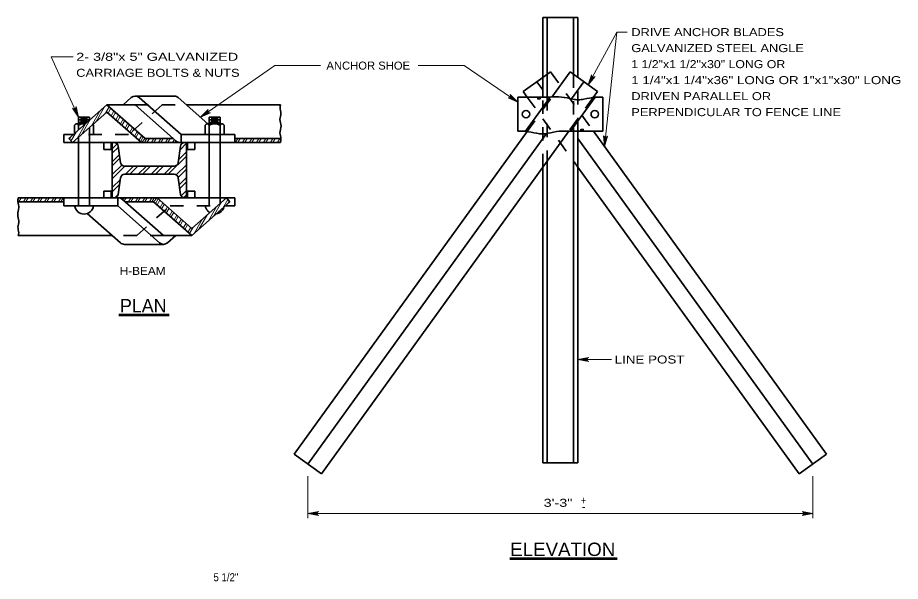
# Model space of a CAD drawing. Extents: x -38.29 to -31.67, y 88.17 to 97.95.
# Drawn here: x -38.29 to -31.67, y 93.73 to 97.95 of the extents above; entities that cross this region are included whole.
import ezdxf
from ezdxf.enums import TextEntityAlignment as Align

# ---------------------------------------------------------------- set-up
doc = ezdxf.new("R2010")
doc.units = 0
doc.header["$LTSCALE"] = 0.024
doc.linetypes.add('SHORT_DASHED', pattern=[2.7, 1.5, -1.2])
for name, color, linetype, lineweight in [('1', 7, 'Continuous', 35), ('10', 7, 'Continuous', 13), ('12', 7, 'Continuous', 53), ('6', 7, 'Continuous', 13)]:
    doc.layers.add(name, color=color, linetype=linetype, lineweight=lineweight)

msp = doc.modelspace()

# ---------------------------------------------------------------- linework, layer by layer
at = {"layer": '1'}
for p, q in [((-34.35494, 97.95427), (-34.09231, 97.95427)), ((-34.35494, 97.95427), (-34.35494, 97.35879)), ((-34.32212, 97.35879), (-34.32212, 97.95427)), ((-34.12515, 97.52935), (-34.12515, 97.95427)), ((-34.09231, 97.95427), (-34.09231, 97.50565)), ((-34.5016, 97.39975), (-34.35494, 97.50565)), ((-34.1504, 97.54758), (-34.28675, 97.35879)), ((-33.94567, 97.39975), (-34.1504, 97.54758)), ((-34.39923, 97.47367), (-34.35494, 97.41233)), ((-34.14069, 97.34537), (-34.04802, 97.47367)), ((-34.50158, 97.39975), (-34.47202, 97.35879)), ((-33.94567, 97.39975), (-33.9771, 97.35621)), ((-37.44183, 97.3544), (-37.50337, 97.3001)), ((-37.41177, 97.36577), (-37.11883, 97.36577)), ((-37.38169, 97.3544), (-37.06833, 97.0779)), ((-37.08877, 97.3544), (-36.86698, 97.15871)), ((-34.542, 97.35879), (-34.542, 97.10225)), ((-34.542, 97.35879), (-34.29921, 97.35879)), ((-34.29921, 97.35879), (-34.48448, 97.10225)), ((-33.96279, 97.35879), (-34.14806, 97.10225)), ((-33.96279, 97.35879), (-33.90527, 97.35879)), ((-33.90527, 97.35879), (-33.90527, 97.10225)), ((-37.62387, 97.3001), (-37.91006, 97.04758)), ((-37.6239, 97.24621), (-37.88333, 97.01729)), ((-37.6239, 97.24621), (-37.36444, 97.01729)), ((-37.62387, 97.3001), (-37.41177, 97.3001)), ((-37.62387, 97.3001), (-37.33771, 97.04758)), ((-37.41177, 97.3001), (-37.10412, 97.02867)), ((-37.02723, 97.3001), (-36.32283, 97.3001)), ((-37.836, 97.20921), (-37.75521, 97.20921)), ((-37.836, 97.20921), (-37.836, 97.15871)), ((-37.836, 97.189), (-37.75521, 97.189)), ((-37.82142, 97.1991), (-37.76979, 97.1991)), ((-37.82142, 97.17892), (-37.76979, 97.17892)), ((-37.75521, 97.20921), (-37.75521, 97.18423)), ((-36.85621, 97.20921), (-36.7754, 97.20921)), ((-36.85621, 97.20921), (-36.85621, 97.15871)), ((-36.85621, 97.189), (-36.7754, 97.189)), ((-36.8416, 97.1991), (-36.79, 97.1991)), ((-36.8416, 97.17892), (-36.79, 97.17892)), ((-36.7754, 97.20921), (-36.7754, 97.15871)), ((-37.86631, 97.14894), (-37.86631, 97.08621)), ((-37.836, 97.16881), (-37.77269, 97.16881)), ((-37.836, 97.14894), (-37.836, 97.11294)), ((-36.88652, 97.14894), (-36.88652, 97.0779)), ((-36.85621, 97.16881), (-36.7754, 97.16881)), ((-36.85621, 97.14894), (-36.85621, 97.0779)), ((-36.7754, 97.14894), (-36.7754, 97.0779)), ((-36.7451, 97.14894), (-36.7451, 97.0779)), ((-37.94712, 97.01729), (-37.94712, 97.0779)), ((-37.94712, 97.0779), (-37.87571, 97.0779)), ((-37.91006, 97.04758), (-37.88333, 97.01729)), ((-37.33771, 97.04758), (-37.36444, 97.01729)), ((-37.33771, 97.04758), (-37.12558, 97.04758)), ((-37.06833, 97.0779), (-37.06833, 97.01729)), ((-37.06833, 97.0779), (-36.66429, 97.0779)), ((-36.66429, 97.0779), (-36.66429, 97.01729)), ((-36.66429, 97.04758), (-36.31919, 97.04758)), ((-34.47346, 97.10027), (-36.22031, 94.68156)), ((-36.11794, 94.60762), (-34.32867, 97.0851)), ((-34.16052, 97.10225), (-36.01558, 94.53371)), ((-34.542, 97.10225), (-34.48448, 97.10225)), ((-34.14806, 97.10225), (-33.90527, 97.10225)), ((-34.12515, 94.6176), (-34.12515, 97.10225)), ((-34.09231, 97.10225), (-34.09231, 94.6176)), ((-34.09231, 97.04871), (-32.32931, 94.60762)), ((-33.97525, 97.10225), (-32.22696, 94.68156)), ((-37.94712, 97.01729), (-36.32283, 97.01729)), ((-37.836, 96.60315), (-37.836, 97.01729)), ((-37.75521, 96.60315), (-37.75521, 97.01729)), ((-37.6466, 96.96679), (-37.6466, 97.01729)), ((-37.59106, 96.96679), (-37.59106, 97.01729)), ((-37.58348, 96.60315), (-37.58348, 97.01729)), ((-37.58348, 97.01729), (-37.56935, 97.01729)), ((-37.53935, 96.99127), (-37.52154, 96.86654)), ((-37.08987, 96.86654), (-37.07204, 96.99127)), ((-37.04204, 97.01729), (-37.02792, 97.01729)), ((-37.02792, 96.60315), (-37.02792, 97.01729)), ((-37.02035, 96.96679), (-37.02035, 97.01729)), ((-36.96479, 96.96679), (-36.96479, 97.01729)), ((-36.85621, 96.60315), (-36.85621, 97.01729)), ((-36.7754, 96.60315), (-36.7754, 97.01729)), ((-37.6466, 96.96679), (-37.59106, 96.96679)), ((-37.02035, 96.96679), (-36.96479, 96.96679)), ((-34.32212, 94.6176), (-34.32212, 96.8785)), ((-37.49154, 96.84052), (-37.11985, 96.84052)), ((-37.49154, 96.77992), (-37.11985, 96.77992)), ((-34.35494, 96.83306), (-34.35494, 94.6176)), ((-34.09231, 96.83306), (-32.43169, 94.53371)), ((-37.52154, 96.7539), (-37.53935, 96.62917)), ((-37.07204, 96.62917), (-37.08987, 96.7539)), ((-37.6466, 96.65365), (-37.59106, 96.65365)), ((-37.6466, 96.60315), (-37.6466, 96.65365)), ((-37.59106, 96.60315), (-37.59106, 96.65365)), ((-37.02035, 96.65365), (-36.96479, 96.65365)), ((-37.02035, 96.60315), (-37.02035, 96.65365)), ((-36.96479, 96.60315), (-36.96479, 96.65365)), ((-36.66429, 96.60315), (-38.28856, 96.60315)), ((-37.94712, 96.54254), (-37.94712, 96.60315)), ((-37.56935, 96.60315), (-37.58348, 96.60315)), ((-37.56935, 96.60315), (-37.58348, 96.60315)), ((-37.54308, 96.54254), (-37.54308, 96.60315)), ((-37.19965, 96.32033), (-37.50727, 96.59177)), ((-37.27371, 96.57285), (-37.24698, 96.60315)), ((-36.98752, 96.37423), (-37.24698, 96.60315)), ((-37.02792, 96.60315), (-37.04204, 96.60315)), ((-37.02792, 96.60315), (-37.04204, 96.60315)), ((-36.98752, 96.37423), (-36.72806, 96.60315)), ((-36.70133, 96.57285), (-36.72806, 96.60315)), ((-36.66429, 96.60315), (-36.66429, 96.54254)), ((-37.94712, 96.57285), (-38.29223, 96.57285)), ((-37.54308, 96.54254), (-37.94712, 96.54254)), ((-37.22971, 96.26604), (-37.54308, 96.54254)), ((-37.27371, 96.57285), (-37.48583, 96.57285)), ((-36.98752, 96.32033), (-37.27371, 96.57285)), ((-36.98752, 96.32033), (-36.70133, 96.57285)), ((-36.66429, 96.54254), (-36.73569, 96.54254)), ((-37.52265, 96.26604), (-37.7719, 96.48598)), ((-37.58417, 96.32033), (-38.28856, 96.32033)), ((-36.98752, 96.32033), (-37.19965, 96.32033)), ((-37.16956, 96.26604), (-37.10804, 96.32033)), ((-37.19965, 96.25469), (-37.49256, 96.25469)), ((-36.01558, 94.53371), (-36.22031, 94.68156)), ((-32.43169, 94.53371), (-32.22696, 94.68156)), ((-34.35494, 94.6176), (-34.09231, 94.6176))]:
    msp.add_line(p, q, dxfattribs=at)
at = {"layer": '1', "linetype": 'SHORT_DASHED'}
for p, q in [((-34.29688, 97.54758), (-34.35494, 97.50565)), ((-34.29688, 97.54758), (-33.97525, 97.10225)), ((-34.12515, 97.52935), (-34.12515, 97.10225)), ((-34.09231, 97.10225), (-34.09231, 97.50565)), ((-34.47346, 97.10027), (-34.28675, 97.35879)), ((-34.47202, 97.35879), (-34.09231, 96.83306)), ((-34.35494, 96.83306), (-34.35494, 97.35879)), ((-34.32212, 97.35879), (-34.32212, 96.8785)), ((-33.9771, 97.35621), (-34.16052, 97.10225)), ((-37.41177, 97.3001), (-37.02723, 97.3001)), ((-37.75521, 97.13035), (-37.75521, 97.0779)), ((-37.7249, 97.14894), (-37.7249, 97.0779)), ((-37.836, 97.05906), (-37.836, 97.01729)), ((-37.75521, 97.0779), (-37.75521, 97.01729)), ((-36.85621, 97.0779), (-36.85621, 97.01729)), ((-36.7754, 97.0779), (-36.7754, 97.01729)), ((-37.836, 96.54254), (-37.836, 96.60315)), ((-37.75521, 96.54254), (-37.75521, 96.60315)), ((-36.85621, 96.54254), (-36.85621, 96.60315)), ((-36.7754, 96.5614), (-36.7754, 96.60315)), ((-37.19965, 96.32033), (-37.58417, 96.32033))]:
    msp.add_line(p, q, dxfattribs=at)
at = {"layer": '1'}
for points in [[(-34.39319, 97.35883), (-34.39319, 97.34477), (-34.376, 97.34477), (-34.376, 97.35879)], [(-37.85117, 97.15871), (-37.836, 97.15871), (-37.78412, 97.15871)], [(-36.87135, 97.15871), (-36.85621, 97.15871), (-36.7754, 97.15871), (-36.76025, 97.15871)], [(-34.0696, 97.10235), (-34.0696, 97.11642), (-34.05242, 97.11642), (-34.05242, 97.10237)]]:
    msp.add_lwpolyline(points, dxfattribs=at)
at = {"layer": '1', "linetype": 'SHORT_DASHED'}
for points in [[(-37.21044, 97.3001), (-37.46227, 97.0779), (-37.81465, 97.0779)], [(-37.40096, 96.32033), (-37.14915, 96.54254), (-36.79675, 96.54254)]]:
    msp.add_lwpolyline(points, dxfattribs=at)
at = {"layer": '1'}
for centre in [(-34.48139, 97.23053), (-33.96587, 97.23053)]:
    msp.add_circle(centre, 0.02778, dxfattribs=at)
for centre, radius, start, end in [((-37.41176, 97.32031), 0.04546, 48.57651, 131.42403), ((-37.11883, 97.32031), 0.04546, 48.5763, 90.18287), ((-37.85116, 97.14207), 0.01663, 24.36946, 155.63054), ((-37.7956, 97.07028), 0.08843, 83.03193, 117.18777), ((-36.87136, 97.14207), 0.01663, 24.36946, 155.63054), ((-36.8158, 97.07028), 0.08843, 62.81223, 117.18777), ((-36.76025, 97.14207), 0.01663, 24.36946, 155.63054), ((-37.56936, 96.98699), 0.0303, 8.12961, 90), ((-37.07406, 97.06275), 0.04546, 228.57644, 270), ((-37.04205, 96.98699), 0.0303, 90, 171.87018), ((-37.49154, 96.87083), 0.0303, 188.13027, 270), ((-37.11986, 96.87083), 0.0303, 270, 351.8694), ((-37.49154, 96.74962), 0.0303, 90, 171.87032), ((-37.11986, 96.74962), 0.0303, 8.1301, 90), ((-37.56936, 96.63345), 0.0303, 270, 351.86927), ((-37.53735, 96.5577), 0.04546, 48.57644, 90), ((-37.04205, 96.63345), 0.0303, 188.12902, 270), ((-37.7956, 96.55349), 0.07155, 188.79741, 351.20259), ((-36.8158, 96.55349), 0.07155, 280.23975, 342.6074), ((-37.49257, 96.30013), 0.04546, 228.5763, 270.18287), ((-37.19964, 96.30013), 0.04546, 228.57651, 311.42403)]:
    msp.add_arc(centre, radius, start, end, dxfattribs=at)
at = {"layer": '1', "linetype": 'SHORT_DASHED'}
for centre, radius, start, end in [((-37.74005, 97.14207), 0.01663, 24.36946, 45.69057), ((-36.8158, 96.55349), 0.07155, 188.79741, 238.32996)]:
    msp.add_arc(centre, radius, start, end, dxfattribs=at)
at = {"layer": '1'}
for points in [[(-34.29921, 97.35879), (-34.2151, 97.35879), (-34.131, 97.34365), (-34.08894, 97.3386), (-34.0469, 97.34365), (-33.96279, 97.35879)], [(-34.14806, 97.10225), (-34.23217, 97.10225), (-34.31627, 97.0871), (-34.35833, 97.08206), (-34.40037, 97.0871), (-34.48448, 97.10225)]]:
    msp.add_spline(points, degree=3, dxfattribs=at)
at = {"layer": '10'}
for p, q in [((-33.80135, 97.84579), (-33.72217, 97.84579)), ((-36.36567, 97.59485), (-36.92213, 97.20737)), ((-36.36567, 97.59485), (-36.02154, 97.59485)), ((-35.29029, 97.59485), (-34.94617, 97.59485)), ((-34.94617, 97.59485), (-34.542, 97.32142)), ((-34.09231, 95.39117), (-33.83912, 95.39117)), ((-36.11794, 94.51673), (-36.11794, 94.2005)), ((-32.32931, 94.51673), (-32.32931, 94.2005)), ((-36.11794, 94.23685), (-32.32931, 94.23685))]:
    msp.add_line(p, q, dxfattribs=at)
for points in [[(-34.01442, 97.4494), (-33.80135, 97.84579), (-33.89325, 96.98871)], [(-37.87706, 97.66137), (-38.04131, 97.66137), (-37.836, 97.20921)], [(-34.01442, 97.4494), (-33.98994, 97.52642), (-33.98908, 97.51902), (-33.9859, 97.51371), (-33.98163, 97.51037), (-33.9765, 97.50867), (-33.97033, 97.50892), (-33.96369, 97.51231), (-34.01442, 97.4494), (-33.97033, 97.50892), (-33.9765, 97.50867), (-34.01442, 97.4494), (-33.98163, 97.51037), (-33.9859, 97.51371), (-34.01442, 97.4494), (-33.98908, 97.51902)], [(-34.542, 97.32142), (-34.61615, 97.35358), (-34.60869, 97.35367), (-34.60308, 97.35631), (-34.59935, 97.36021), (-34.59712, 97.36515), (-34.59675, 97.37131), (-34.59944, 97.37827), (-34.542, 97.32142), (-34.59675, 97.37131), (-34.59712, 97.36515), (-34.542, 97.32142), (-34.59935, 97.36021), (-34.60308, 97.35631), (-34.542, 97.32142), (-34.60869, 97.35367)], [(-37.836, 97.20921), (-37.88242, 97.27537), (-37.87602, 97.27156), (-37.86985, 97.2709), (-37.86462, 97.27227), (-37.86017, 97.27529), (-37.85663, 97.28037), (-37.85529, 97.28771), (-37.836, 97.20921), (-37.85663, 97.28037), (-37.86017, 97.27529), (-37.836, 97.20921), (-37.86462, 97.27227), (-37.86985, 97.2709), (-37.836, 97.20921), (-37.87602, 97.27156)], [(-36.92213, 97.20737), (-36.86546, 97.26498), (-36.86804, 97.258), (-36.8676, 97.25183), (-36.86531, 97.24694), (-36.8615, 97.24308), (-36.85587, 97.24052), (-36.84844, 97.24054), (-36.92213, 97.20737), (-36.85587, 97.24052), (-36.8615, 97.24308), (-36.92213, 97.20737), (-36.86531, 97.24694), (-36.8676, 97.25183), (-36.92213, 97.20737), (-36.86804, 97.258)], [(-33.89325, 96.98871), (-33.89958, 97.06929), (-33.89602, 97.06275), (-33.89106, 97.05904), (-33.88585, 97.05756), (-33.88048, 97.05792), (-33.87483, 97.06048), (-33.86996, 97.06612), (-33.89325, 96.98871), (-33.87483, 97.06048), (-33.88048, 97.05792), (-33.89325, 96.98871), (-33.88585, 97.05756), (-33.89106, 97.05904), (-33.89325, 96.98871), (-33.89602, 97.06275)], [(-34.09231, 95.39117), (-34.01288, 95.40606), (-34.019, 95.40181), (-34.02217, 95.3965), (-34.02306, 95.39117), (-34.02217, 95.38583), (-34.019, 95.38052), (-34.01288, 95.37627), (-34.09231, 95.39117), (-34.019, 95.38052), (-34.02217, 95.38583), (-34.09231, 95.39117), (-34.02306, 95.39117), (-34.02217, 95.3965), (-34.09231, 95.39117), (-34.019, 95.40181)], [(-36.11794, 94.23685), (-36.0385, 94.25175), (-36.04462, 94.24752), (-36.04779, 94.24219), (-36.04871, 94.23685), (-36.04779, 94.23154), (-36.04462, 94.22621), (-36.0385, 94.22196), (-36.11794, 94.23685), (-36.04462, 94.22621), (-36.04779, 94.23154), (-36.11794, 94.23685), (-36.04871, 94.23685), (-36.04779, 94.24219), (-36.11794, 94.23685), (-36.04462, 94.24752)], [(-32.32931, 94.23685), (-32.40875, 94.22196), (-32.40265, 94.22621), (-32.39948, 94.23154), (-32.39856, 94.23685), (-32.39948, 94.24219), (-32.40265, 94.24752), (-32.40875, 94.25175), (-32.32931, 94.23685), (-32.40265, 94.24752), (-32.39948, 94.24219), (-32.32931, 94.23685), (-32.39856, 94.23685), (-32.39948, 94.23154), (-32.32931, 94.23685), (-32.40265, 94.22621)]]:
    msp.add_lwpolyline(points, dxfattribs=at)
at = {"layer": '10', "lineweight": 35}
for points in [[(-36.32283, 97.3001), (-36.32604, 97.27829), (-36.31987, 97.23617), (-36.3266, 97.19067), (-36.31819, 97.14238), (-36.3266, 97.09069), (-36.31931, 97.04631), (-36.32283, 97.01729)], [(-38.28856, 96.32033), (-38.28535, 96.34215), (-38.29154, 96.38427), (-38.28481, 96.42977), (-38.29323, 96.47808), (-38.28481, 96.52975), (-38.2921, 96.57412), (-38.28856, 96.60315)]]:
    msp.add_spline(points, degree=3, dxfattribs=at)
at = {"layer": '12'}
for p, q in [((-37.53454, 95.72606), (-37.15738, 95.72606)), ((-34.60219, 93.89946), (-33.79835, 93.89946))]:
    msp.add_line(p, q, dxfattribs=at)
at = {"layer": '6'}
for p, q in [((-37.74069, 97.14317), (-37.67727, 97.253)), ((-37.70502, 97.17462), (-37.6416, 97.28446)), ((-37.63369, 97.23756), (-37.60646, 97.28473)), ((-37.61548, 97.23881), (-37.59488, 97.2745)), ((-37.59229, 97.21835), (-37.57169, 97.25404)), ((-37.58071, 97.20812), (-37.5601, 97.24381)), ((-37.812, 97.08023), (-37.74858, 97.19006)), ((-37.55752, 97.18767), (-37.53692, 97.22337)), ((-37.54594, 97.17744), (-37.52533, 97.21315)), ((-37.52275, 97.15698), (-37.50215, 97.19269)), ((-37.51117, 97.14675), (-37.49056, 97.18246)), ((-37.84767, 97.04875), (-37.78425, 97.1586)), ((-37.48798, 97.12631), (-37.46737, 97.162)), ((-37.4764, 97.11608), (-37.45579, 97.15177)), ((-37.45321, 97.09562), (-37.4326, 97.13131)), ((-37.44163, 97.0854), (-37.421, 97.12108)), ((-37.90448, 97.04127), (-37.89125, 97.06419)), ((-37.89392, 97.02927), (-37.85558, 97.09567)), ((-37.41844, 97.06494), (-37.39783, 97.10065)), ((-37.40685, 97.05471), (-37.38623, 97.09042)), ((-37.38367, 97.03425), (-37.36306, 97.06996)), ((-37.37208, 97.02404), (-37.35146, 97.05973)), ((-37.34098, 97.01729), (-37.32348, 97.04758)), ((-37.32348, 97.01729), (-37.30598, 97.04758)), ((-37.2885, 97.01729), (-37.271, 97.04758)), ((-37.271, 97.01729), (-37.2535, 97.04758)), ((-37.236, 97.01729), (-37.21852, 97.04758)), ((-37.2185, 97.01729), (-37.20102, 97.04758)), ((-37.18352, 97.01729), (-37.16602, 97.04758)), ((-37.16602, 97.01729), (-37.14852, 97.04758)), ((-36.65867, 97.01729), (-36.64117, 97.04758)), ((-36.64117, 97.01729), (-36.62367, 97.04758)), ((-36.60617, 97.01729), (-36.58869, 97.04758)), ((-36.58869, 97.01729), (-36.57119, 97.04758)), ((-36.55369, 97.01729), (-36.53619, 97.04758)), ((-36.53619, 97.01729), (-36.51871, 97.04758)), ((-36.50121, 97.01729), (-36.48371, 97.04758)), ((-36.48371, 97.01729), (-36.46621, 97.04758)), ((-36.44871, 97.01729), (-36.43123, 97.04758)), ((-36.43123, 97.01729), (-36.41373, 97.04758)), ((-36.39623, 97.01729), (-36.37873, 97.04758)), ((-36.37873, 97.01729), (-36.36125, 97.04758)), ((-36.34375, 97.01729), (-36.32625, 97.04758)), ((-37.58348, 96.97094), (-37.54698, 97.00742)), ((-37.58348, 96.93879), (-37.53831, 96.98396)), ((-37.13102, 97.01729), (-37.1176, 97.04054)), ((-37.11354, 97.01729), (-37.10602, 97.03031)), ((-37.07592, 96.96425), (-37.02792, 97.01223)), ((-36.32625, 97.01729), (-36.32194, 97.02477)), ((-37.58348, 96.8745), (-37.53027, 96.92771)), ((-37.16381, 96.77992), (-37.02792, 96.91579)), ((-37.08662, 96.88925), (-37.02792, 96.94794)), ((-37.58348, 96.84235), (-37.52627, 96.89958)), ((-37.58348, 96.77808), (-37.51256, 96.849)), ((-37.104, 96.77544), (-37.02792, 96.85152)), ((-37.58348, 96.74594), (-37.4889, 96.84052)), ((-37.48523, 96.77992), (-37.4246, 96.84052)), ((-37.45308, 96.77992), (-37.39248, 96.84052)), ((-37.38879, 96.77992), (-37.32819, 96.84052)), ((-37.35665, 96.77992), (-37.29604, 96.84052)), ((-37.29237, 96.77992), (-37.23177, 96.84052)), ((-37.26023, 96.77992), (-37.19962, 96.84052)), ((-37.19596, 96.77992), (-37.13533, 96.84052)), ((-37.09044, 96.75685), (-37.02792, 96.81937)), ((-37.58348, 96.68165), (-37.52325, 96.74187)), ((-37.08227, 96.70075), (-37.02792, 96.75508)), ((-37.07825, 96.67262), (-37.02792, 96.72296)), ((-37.58348, 96.64952), (-37.52862, 96.70437)), ((-37.06829, 96.61831), (-37.02792, 96.65867)), ((-38.28517, 96.60315), (-38.28948, 96.59567)), ((-38.26767, 96.60315), (-38.28515, 96.57285)), ((-38.23267, 96.60315), (-38.25017, 96.57285)), ((-38.21517, 96.60315), (-38.23267, 96.57285)), ((-38.18019, 96.60315), (-38.19769, 96.57285)), ((-38.16269, 96.60315), (-38.18019, 96.57285)), ((-38.12771, 96.60315), (-38.14519, 96.57285)), ((-38.11021, 96.60315), (-38.12769, 96.57285)), ((-38.07521, 96.60315), (-38.09271, 96.57285)), ((-38.05771, 96.60315), (-38.07521, 96.57285)), ((-38.02273, 96.60315), (-38.04023, 96.57285)), ((-38.00523, 96.60315), (-38.02273, 96.57285)), ((-37.97025, 96.60315), (-37.98773, 96.57285)), ((-37.95275, 96.60315), (-37.97023, 96.57285)), ((-37.56529, 96.60342), (-37.53933, 96.62937)), ((-37.49788, 96.60315), (-37.5054, 96.59013)), ((-37.48038, 96.60315), (-37.49381, 96.5799)), ((-37.44537, 96.60315), (-37.46287, 96.57285)), ((-37.4279, 96.60315), (-37.44537, 96.57285)), ((-37.3929, 96.60315), (-37.4104, 96.57285)), ((-37.3754, 96.60315), (-37.3929, 96.57285)), ((-37.34042, 96.60315), (-37.3579, 96.57285)), ((-37.32292, 96.60315), (-37.34042, 96.57285)), ((-37.28792, 96.60315), (-37.30542, 96.57285)), ((-37.27044, 96.60315), (-37.28792, 96.57285)), ((-37.23933, 96.59642), (-37.25994, 96.56071)), ((-37.22775, 96.58619), (-37.24835, 96.55048)), ((-37.05019, 96.60427), (-37.02792, 96.62652)), ((-36.7175, 96.59117), (-36.75583, 96.52477)), ((-36.70692, 96.57919), (-36.72017, 96.55625)), ((-37.20456, 96.56573), (-37.22517, 96.53002)), ((-37.19296, 96.5555), (-37.21358, 96.51981)), ((-37.16979, 96.53504), (-37.1904, 96.49935)), ((-37.15819, 96.52481), (-37.17881, 96.48913)), ((-36.7994, 96.54021), (-36.86281, 96.43037)), ((-36.76373, 96.57169), (-36.82715, 96.46185)), ((-37.13502, 96.50437), (-37.15563, 96.46867)), ((-37.12342, 96.49415), (-37.14404, 96.45844)), ((-37.10025, 96.47369), (-37.12085, 96.43798)), ((-37.08865, 96.46346), (-37.10927, 96.42775)), ((-36.9064, 96.44581), (-36.96981, 96.33598)), ((-36.87073, 96.47727), (-36.93415, 96.36744)), ((-37.06548, 96.443), (-37.08608, 96.40731)), ((-37.05387, 96.43277), (-37.07448, 96.39708)), ((-37.03069, 96.41231), (-37.05131, 96.37662)), ((-37.0191, 96.40208), (-37.03971, 96.3664)), ((-36.99592, 96.38165), (-37.01654, 96.34594)), ((-36.97771, 96.38287), (-37.00494, 96.33571))]:
    msp.add_line(p, q, dxfattribs=at)

# ---------------------------------------------------------------- texts
at = {"layer": '12'}
for s, width, p in [('DRIVE ANCHOR BLADES', 1.2, (-33.69184, 97.81578)), ('GALVANIZED STEEL ANGLE', 1.2, (-33.69184, 97.69578)), ('2- 3/8"x 5" GALVANIZED', 1.35, (-37.85433, 97.63076)), ('1 1/2"x1 1/2"x30" LONG OR', 1.15, (-33.69184, 97.57578)), ('CARRIAGE BOLTS & NUTS', 1.2, (-37.85433, 97.51076)), ('ANCHOR SHOE', 1.05, (-35.97794, 97.56484)), ('1 1/4"x1 1/4"x36" LONG OR 1"x1"x30" LONG', 1.25, (-33.69184, 97.45578)), ('DRIVEN PARALLEL OR', 1.2, (-33.69184, 97.33578)), ('PERPENDICULAR TO FENCE LINE', 1.2, (-33.69184, 97.21578)), ('LINE POST', 1.25, (-33.8164, 95.36117))]:
    msp.add_text(s, height=0.06, dxfattribs=dict(at, width=width)).set_placement(p)
for s, height, width, p in [('H-BEAM', 0.06, 1.1, (-37.35616, 96.02553)), ('3\'-3"', 0.06, 1.35, (-34.24131, 94.28672)), ('+', 0.06, 0.85, (-34.04937, 94.30401)), ('ELEVATION', 0.1, 1.05, (-34.20588, 93.91806)), ('5 1/2"', 0.06, 0.9, (-36.73177, 93.72877))]:
    msp.add_text(s, height=height, dxfattribs=dict(at, width=width)).set_placement(p, align=Align.CENTER)
for s, height, p in [('PLAN', 0.1, (-37.35173, 95.74467)), ('-', 0.06, (-34.04937, 94.25752))]:
    msp.add_text(s, height=height, dxfattribs=at).set_placement(p, align=Align.CENTER)

doc.saveas('drawing.dxf')
